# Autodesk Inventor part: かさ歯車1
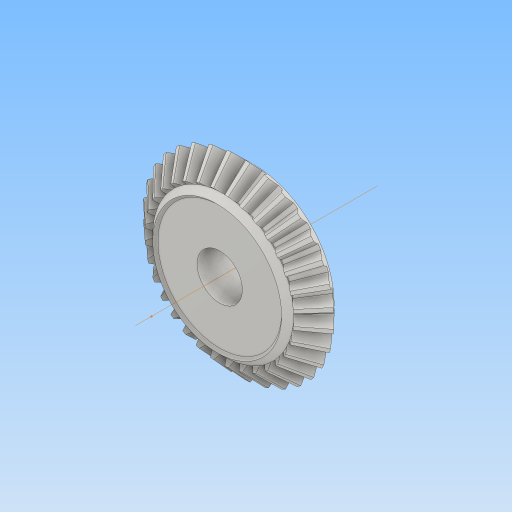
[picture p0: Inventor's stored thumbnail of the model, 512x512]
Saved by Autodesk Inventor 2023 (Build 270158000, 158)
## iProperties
CustomPartVersion: 1
Created: 2024-05
Part Number: かさ歯車1
Material: Steel, Mild
Document SubType Name: Modeling
Designer: kumagai
Categories: <?xml version="1.0" encoding="UTF-16"?> <MemberInstance><Categories><FamilyTemplate><FamilyTemplateParameter ValueType="xs:double" Id="1" ObjectReferenceKey="da
Mass: 60.9118 g
Surface Area: 34.3074 cm^2
Volume: 7.7496 cm^3
Density: 7.86 g/cm^3
Appearance: Steel
Author: kumagai
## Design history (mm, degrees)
node "上側の点"
node "メッシュ平面2"
sketch "歯のボディ スケッチ"
  geometry: L1 (0, 0)-(15.151, -16.849); L2 (15.151, -16.849)-(16.707, -15.293); L3 (16.707, -15.293)-(0, 0); L4 (16, -16)-(0, 0); L5 (11.803, -13.125)-(13.015, -11.914); L6 (15.151, -16.849)-(11.803, -13.125); L7 (16.707, -15.293)-(13.015, -11.914); L8 (0, -39.387)-(0, 6.564) reference; L9 (0, -16)-(16.707, -16)
  constraints: 16 end point, 4 point on line, 3 perpendicular, 2 collinear, 1 horizontal alignment, 1 vertical alignment
  dimensions: "d0" = 32 diameter of L4.start L8 (= da_de); "d1" = 30.30294 diameter of L1.end L8 (= da_dfe); "d2" = 33.41421 diameter of L2.end L8 (= da_dae); "d3" = 5 distance between parallel lines of L2 L5 (= da_b); "d4" = 15.29289 vertical distance of L2.end L1.start (= da_ve)
revolve "歯のボディ" sketch "歯のボディ スケッチ" stored, may be unused: angle "d5" = 90 deg
node "始点"
node "歯の平面"
sketch "開始スケッチ"
  geometry: L1 (0, -23.505)-(0, 10.645) reference; L2 (-0.366, -1.464)-(0.366, -1.464); A1 r 8.083 centre (-8.298, -3.019) between (-0.366, -1.464) and (-1.666, 1.603); A2 r 8.083 centre (8.298, -3.019) between (1.666, 1.603) and (0.366, -1.464); A3 r 24.287 centre (0, -22.627) between (1.666, 1.603) and (-1.666, 1.603); 1 further point
  constraints: 6 point on circle, 3 centre point, 3 symmetric about line, 2 end point, 1 coincident, 1 perpendicular, 1 other
  dimensions: "d7" = 8.08317 radius of A1 (= fd_rr); "d8" = 8.29774 horizontal distance of point (0, -22.627) A1.centre (= fd_x); "d9" = 19.60833 vertical distance of point (0, -22.627) A1.centre (= fd_y); "d57" = 24.28742 radius of A3 (= 0.5 x fd_dva + 0.3 x da_he); "d58" = 21.16342 distance from line of A3.centre L2 (= 0.5 x fd_dva - 1.12 x da_he)
node "終了側の点"
  node "終了平面"
sketch "終了側スケッチ"
  geometry: L1 (0, -15.354)-(0, 6.953) reference; L2 (-0.283, -1.133)-(0.283, -1.133); A1 r 6.258 centre (-6.424, -2.337) between (-0.283, -1.133) and (-1.29, 1.241); A2 r 6.258 centre (6.424, -2.337) between (1.29, 1.241) and (0.283, -1.133); A3 r 18.803 centre (0, -17.517) between (1.29, 1.241) and (-1.29, 1.241); 1 further point
  constraints: 6 point on circle, 3 centre point, 3 symmetric about line, 2 end point, 1 coincident, 1 other
  dimensions: "d12" = 6.25773 radius of A1 (computed from fd_rr, fd_ratio); "d15" = 6.42384 horizontal distance of A1.centre point (0, -17.517) (computed from fd_x, fd_ratio); "d16" = 15.18014 vertical distance of A1.centre point (0, -17.517) (computed from fd_y, fd_ratio); "d59" = 18.80254 radius of A3 (computed from d57, fd_ratio); "d60" = 16.38404 distance from line of A3.centre L2 (computed from d58, fd_ratio)
feature "Loft" sketch "終了側スケッチ" dims "d17" = 0, "d18" = 90 deg, "d19" = 0, "d20" = 90 deg, "d89" = 0, "da_teethtype" = 0 [user parameter]
sketch "3D スケッチ(右)"
  node "Helical Curve Right" dims "d65" = 173.72889 (computed from da_dm, da_delta, da_beta), "d66" = 31.5, "d67" = 32 (= da_de), "d68" = -45 deg (= -da_delta), "d69" = 3.61332 (computed from fd_loft, da_delta)
node "終了平面(右)"
sketch "終了側スケッチ(右)"
  geometry: L1 (0, -23.46)-(0, 9.709) reference; L2 (-0.283, -1.133)-(0.283, -1.133); A1 r 6.258 centre (-6.424, -2.337) between (-0.283, -1.133) and (-1.29, 1.241); A2 r 6.258 centre (6.424, -2.337) between (1.29, 1.241) and (0.283, -1.133); A3 r 18.803 centre (0, -17.517) between (1.29, 1.241) and (-1.29, 1.241); 1 further point
  constraints: 6 point on circle, 3 centre point, 3 symmetric about line, 2 end point, 1 coincident, 1 perpendicular, 1 other
  dimensions: "d70" = 6.42384 horizontal distance of A3.centre A1.centre (computed from fd_x, fd_ratio); "d71" = 15.18014 vertical distance of point (0, -17.517) A1.centre (computed from fd_y, fd_ratio); "d72" = 6.25773 radius of A1 (computed from fd_rr, fd_ratio); "d73" = 16.38404 distance from line of point (0, -17.517) L2 (computed from d58, fd_ratio); "d74" = 18.80254 radius of A3 (computed from d57, fd_ratio)
feature "ロフト(右)" sketch "終了側スケッチ(右)" dims "d75" = 0, "d77" = 0, "d79" = 0, "d80" = 90 deg, "d85" = 20, "d92" = 90 deg, "d93" = 90 deg, "da_teethtype" = 0 [user parameter]
sketch "3D スケッチ(左)"
  node "Helical Curve Left" dims "d26" = 173.72889 (computed from da_dm, da_delta, da_beta), "d27" = 3.61332 (computed from fd_loft, da_delta), "d28" = 32 (= da_de), "d29" = -45 deg (= -da_delta)
node "終了平面(左)"
sketch "終了側スケッチ(左)" dims "d56" = 9.20604 (derived)
  geometry: L1 (0, -29.116)-(0, 12.094) reference; L2 (-0.283, -1.128)-(0.283, -1.128); A1 r 6.258 centre (-6.424, -2.332) between (-0.283, -1.128) and (-1.29, 1.246); A2 r 6.258 centre (6.424, -2.332) between (1.29, 1.246) and (0.283, -1.128); A3 r 18.803 centre (0, -17.512) between (1.29, 1.246) and (-1.29, 1.246); 2 further points; 1 other entity
  constraints: 6 point on circle, 3 centre point, 3 symmetric about line, 2 end point, 1 coincident, 2 other
  dimensions: "d30" = 6.25773 radius of A1 (computed from fd_rr, fd_ratio); "d31" = 6.42384 horizontal distance of point (0, -17.512) A1.centre (computed from fd_x, fd_ratio); "d32" = 15.18014 vertical distance of A1.centre point (0, -17.512) (computed from fd_y, fd_ratio); "d61" = 18.80254 radius of A3 (computed from d57, fd_ratio); "d62" = 16.38404 distance from line of point (0, -17.512) L2 (computed from d58, fd_ratio)
feature "ロフト(左)" sketch "終了側スケッチ(左)" dims "d35" = 0, "d37" = 0, "d39" = 0, "d40" = 90 deg, "d84" = 10, "d90" = 90 deg, "d91" = 90 deg, "da_teethtype" = 0 [user parameter]
sketch "ボディ スケッチ"
  geometry: L1 (0, -35.038)-(0, -19.531) reference; L2 (15.151, -16.849)-(11.803, -13.125) reference; L3 (11.803, -13.125)-(0, -13.125); L4 (15.151, -16.849)-(0, -16.849); L5 (16, -16)-(0, 0) reference; L6 (11.803, -13.125)-(13.015, -11.914) reference; L7 (0, 0)-(15.151, -16.849) reference; L8 (12.323, -12.606)-(10.909, -14.02); L9 (10.909, -14.02)-(9.848, -12.959); L10 (9.848, -12.959)-(11.262, -11.545); L11 (11.262, -11.545)-(12.323, -12.606); L12 (15.151, -16.849)-(14, -18); L13 (14, -18)-(0, -18); L14 (0, -18)-(0, -16.849); L15 (0, -12)-(0, -13.125); L16 (10.808, -12)-(0, -12); 2 further points
  constraints: 22 end point, 6 point on line, 3 parallel, 2 horizontal, 2 perpendicular, 1 collinear
  dimensions: "d94" = 0.2 distance between parallel lines of L11 L5; "d95" = 1.5 distance between parallel lines of L6 L10; "d96" = 2 distance between parallel lines of L9 L11; "d97" = 18 distance from line of L5.end L13; "d98" = 14 distance from line of L1 L12.end; "d102" = 12 distance from line of L5.end L16
revolve "固定ボディ" sketch "ボディ スケッチ" stored, may be unused: angle "d46" = 360 deg
sketch "Sketch6"
  geometry: L1 (16, -16)-(0, 0) reference; L2 (0, -37.8)-(0, 6.3) reference
feature "ピッチ円直径" sketch "Sketch6" dims angle "d47" = 90 deg
sketch "スケッチ8"
  geometry: C1 r 3.95 at (0, 0); 1 further point
  constraints: 1 centre point, 1 coincident
  dimensions: "d99" = 7.9 diameter of C1
extrude "押し出し1" cut sketch "スケッチ8" extent not by distance; stored distance "d100" = 0; taper "d101" = 0 deg
body "Solid1"
pattern_circular "Circular Pattern" dims angle "d22" = 360 deg, "d88" = 0, "da_teethtype" = 0 [user parameter]
pattern_circular "放射状パターン(右)" dims angle "d82" = 360 deg, "da_teethtype" = 0 [user parameter]
pattern_circular "放射状パターン(左)" dims angle "d42" = 360 deg, "da_teethtype" = 0 [user parameter]
body "Srf1"
other parameters: "da_b" = 5 [user parameter; used in 2 equation terms], "da_de" = 32 [user parameter; used in 4 equation terms], "da_dae" = 33.41421 [user parameter; used in 2 equation terms], "da_dfe" = 30.30294 [user parameter; used in 1 equation term], "da_le" = 22.62742 [user parameter; used in 1 equation term], "da_omega" = 90 deg [user parameter; used in 1 equation term], "da_beta" = 0 [user parameter; used in 2 equation terms], "da_delta" = 45 deg [user parameter; used in 8 equation terms], "da_alpha" = 20 deg [user parameter; used in 2 equation terms], "da_he" = 2.2 [user parameter; used in 4 equation terms], "da_ve" = 15.29289 [user parameter; used in 1 equation term], "fd_dv" = 45.25483 (computed from da_de, da_delta) [user parameter; used in 1 equation term], "fd_dva" = 47.25483 (computed from da_dae, da_delta) [user parameter; used in 3 equation terms], "fd_dvb" = 42.52563 (computed from fd_dv, da_alpha) [user parameter; used in 2 equation terms], "da_zv" = 452.54834 [user parameter; used in 1 equation term], "fd_loft" = 5.11 (= da_b + 0.05 x da_he) [user parameter; used in 4 equation terms], "fd_ratio" = 7.74168 (computed from da_le, fd_loft) [user parameter; used in 15 equation terms], "fd_rr" = 8.08317 (computed from fd_dd, fd_dvb) [user parameter; used in 6 equation terms], "fd_angle" = 0.35096 (computed from da_zv) [user parameter; used in 4 equation terms], "fd_x1" = 0.79396 (computed from da_dvw, fd_angle) [user parameter; used in 1 equation term], "fd_y1" = 22.61348 (computed from da_dvw, fd_angle) [user parameter; used in 1 equation term], "fd_x2" = 7.50378 (computed from fd_rr, fd_angle2, fd_angle) [user parameter; used in 1 equation term], "fd_y2" = 3.00515 (computed from fd_rr, fd_angle2, fd_angle) [user parameter; used in 1 equation term], "fd_x" = 8.29774 (= fd_x1 + fd_x2) [user parameter; used in 4 equation terms], "fd_y" = 19.60833 (= fd_y1 - fd_y2) [user parameter; used in 4 equation terms], "fd_angle2" = 3.45829 (computed from fd_dvb, fd_dd, da_alpha) [user parameter; used in 2 equation terms], "fd_dd" = 45.49483 (= fd_dva - 0.8 x da_he) [user parameter; used in 2 equation terms], "da_dvw" = 45.25483 [user parameter; used in 2 equation terms], "d11" = 5.11 (= fd_loft), "da_dm" = 28.46447 [user parameter; used in 2 equation terms], "da_x" = 0 [user parameter], "da_m" = 1 [user parameter], "d48" = 0, "d49" = 0, "d50" = 90 deg (= da_omega), "d51" = 0.98175 (computed from da_z), "d52" = 0, "d53" = 0, "d54" = 0
